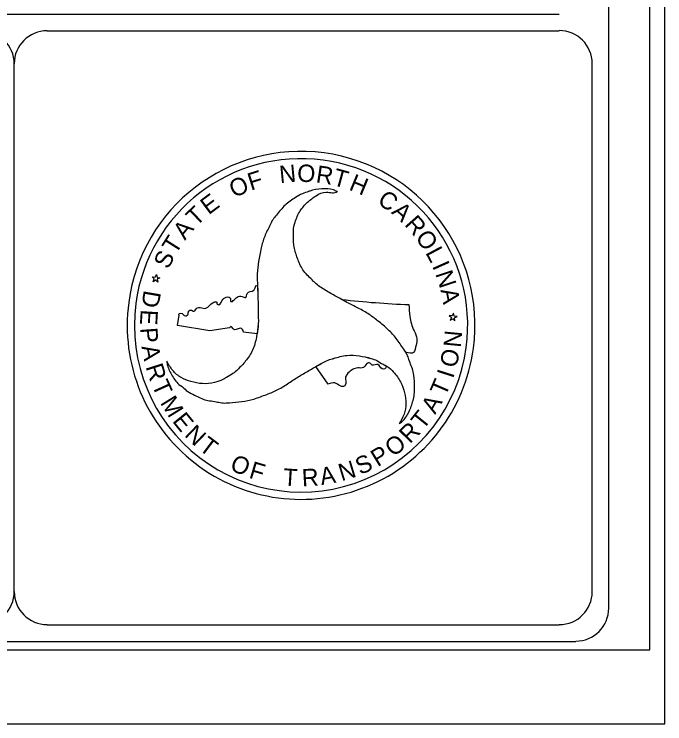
# Model space of a CAD drawing. Extents: x 2163579 to 2286010, y 210234 to 425257.
# Drawn here: x 2258732 to 2271355, y 331036 to 344798 of the extents above; entities that cross this region are included whole.
import ezdxf

# ---------------------------------------------------------------- set-up
doc = ezdxf.new("R2010")
doc.units = 0
for name, color, linetype in [('Sheet Cutting Line CELL', 7, 'Continuous'), ('Sheet Plot Border Inside CELL', 7, 'Continuous'), ('Sheet Plot Border Outside CELL', 7, 'Continuous'), ('Sheet Title CELL', 7, 'Continuous')]:
    doc.layers.add(name, color=color, linetype=linetype)

msp = doc.modelspace()

# ---------------------------------------------------------------- linework, layer by layer
at = {"layer": 'Sheet Cutting Line CELL'}
msp.add_line((2163579, 331036), (2271355, 331036), dxfattribs=at)
at = {"layer": 'Sheet Plot Border Inside CELL'}
msp.add_lwpolyline([(2164411, 332472), (2271067, 332472), (2271067, 399999), (2164411, 399999)], close=True, dxfattribs=at)
at = {"layer": 'Sheet Plot Border Outside CELL'}
msp.add_lwpolyline([(2271355, 401435), (2163579, 401435), (2163579, 331036), (2271355, 331036)], close=True, dxfattribs=at)
at = {"layer": 'Sheet Title CELL'}
for p, q in [((2178427, 344796), (2269307, 344796)), ((2259372, 344476), (2269307, 344476)), ((2258732, 333596), (2258732, 343836)), ((2265005, 341366), (2264998, 341359)), ((2265005, 341366), (2264998, 341359)), ((2261451, 339663), (2261409, 339704)), ((2261409, 339704), (2261468, 339696)), ((2261427, 339610), (2261451, 339663)), ((2261476, 339639), (2261427, 339610)), ((2261468, 339696), (2261491, 339748)), ((2261519, 339598), (2261476, 339639)), ((2261491, 339748), (2261503, 339692)), ((2261503, 339692), (2261561, 339684)), ((2261561, 339684), (2261509, 339656)), ((2261509, 339656), (2261519, 339598)), ((2265089, 339264), (2265089, 339264)), ((2261899, 338762), (2261933, 338963)), ((2267231, 338949), (2267174, 338956)), ((2267174, 338956), (2267217, 338916)), ((2267256, 339000), (2267231, 338949)), ((2267269, 338944), (2267256, 339000)), ((2267217, 338916), (2267193, 338863)), ((2267193, 338863), (2267242, 338891)), ((2267242, 338891), (2267284, 338851)), ((2267326, 338938), (2267269, 338944)), ((2267274, 338909), (2267326, 338938)), ((2267284, 338851), (2267274, 338909)), ((2262530, 338654), (2261899, 338762)), ((2262908, 338713), (2262530, 338654)), ((2263447, 338596), (2263182, 338634)), ((2267642, 338319), (2267642, 338319)), ((2264822, 337623), (2264582, 337965)), ((2264582, 337965), (2264582, 337965))]:
    msp.add_line(p, q, dxfattribs=at)
for points in [[(2270267, 333276), (2270267, 399195)], [(2269947, 333596), (2269947, 343836)], [(2259373, 332956), (2269307, 332956)], [(2174907, 332635), (2269627, 332635)]]:
    msp.add_lwpolyline(points, dxfattribs=at)
for centre, radius, start, end in [((2258092, 343836), 640, 0, 90), ((2259372, 343836), 640, 90, 180), ((2269307, 343839), 640, 0, 90), ((2264298, 338763), 3374, 352.4211, 172.4211), ((2264298, 338763), 3233, 352.4211, 172.4211), ((2267091, 356940), 17788, 258.0996, 258.1992), ((2267091, 356940), 17788, 263.5387, 267.7447), ((2264298, 338763), 3374, 172.4211, 352.4211), ((2264298, 338763), 3233, 172.4211, 352.4211), ((2258093, 333600), 640, 270, 360), ((2259373, 333600), 640, 180, 270), ((2269307, 333599), 640, 270, 360), ((2269627, 333279), 640, 270, 360)]:
    msp.add_arc(centre, radius, start, end, dxfattribs=at)
for points in [[(2264998, 341359), (2264925, 341389), (2264702, 341410), (2264466, 341368), (2264445, 341359), (2264324, 341315), (2264192, 341242), (2263988, 341094), (2263821, 340902), (2263754, 340819), (2263698, 340713), (2263592, 340487), (2263523, 340264), (2263473, 340000), (2263446, 339765), (2263453, 339521), (2263462, 339275), (2263466, 339036), (2263467, 338791), (2263436, 338552), (2263432, 338531), (2263356, 338282), (2263223, 338073), (2263065, 337903), (2262975, 337827), (2262852, 337755), (2262781, 337713), (2262620, 337656), (2262383, 337633), (2262161, 337675), (2261970, 337752), (2261810, 337888), (2261694, 338066)], [(2266200, 336853), (2266259, 336899), (2266390, 337082), (2266471, 337308), (2266477, 337330), (2266496, 337458), (2266499, 337610), (2266476, 337860), (2266390, 338099), (2266354, 338200), (2266289, 338302), (2266146, 338506), (2265989, 338677), (2265784, 338852), (2265594, 338991), (2265379, 339111), (2265162, 339224), (2264955, 339339), (2264738, 339463), (2264549, 339608), (2264534, 339623), (2264353, 339815), (2264239, 340035), (2264170, 340255), (2264153, 340369), (2264152, 340514), (2264148, 340597), (2264182, 340764), (2264280, 340982), (2264426, 341151), (2264589, 341278), (2264787, 341348), (2264998, 341359), (2265005, 341366)], [(2261933, 338963), (2261928, 338982), (2261965, 339000), (2262054, 338949), (2262107, 338983), (2262111, 339024), (2262154, 339059), (2262216, 339038), (2262285, 339105), (2262340, 339110), (2262453, 339095), (2262605, 339212), (2262662, 339213), (2262671, 339175), (2262705, 339164), (2262777, 339267), (2262794, 339281), (2262905, 339309), (2262930, 339285), (2262931, 339234), (2262945, 339223), (2262983, 339243), (2263038, 339296), (2263130, 339329), (2263226, 339304), (2263254, 339382), (2263379, 339444), (2263409, 339488), (2263421, 339534)], [(2263453, 339527), (2263453, 339521), (2263462, 339275), (2263466, 339036), (2263467, 338791), (2263446, 338596)], [(2266334, 338239), (2266289, 338302), (2266146, 338506), (2265989, 338677), (2265784, 338852), (2265594, 338991), (2265379, 339111), (2265162, 339224), (2265089, 339264)], [(2266390, 339165), (2266408, 338935), (2266490, 338657), (2266547, 338503), (2266528, 338380), (2266480, 338236), (2266335, 338240)], [(2263182, 338634), (2263163, 338686), (2263114, 338708), (2263039, 338680), (2262987, 338690), (2262935, 338740), (2262908, 338713)], [(2261694, 338066), (2261707, 337988), (2261800, 337784), (2261953, 337600), (2261971, 337588), (2262072, 337503), (2262201, 337427), (2262431, 337322), (2262679, 337277), (2262784, 337258), (2262909, 337263), (2263152, 337285), (2263379, 337335), (2263635, 337425), (2263849, 337518), (2264060, 337647), (2264267, 337780), (2264473, 337900), (2264686, 338022), (2264907, 338117), (2264931, 338123), (2265185, 338182), (2265430, 338172), (2265653, 338122), (2265768, 338081), (2265888, 338008), (2265965, 337970), (2266092, 337857), (2266229, 337665), (2266304, 337453), (2266333, 337246), (2266295, 337041), (2266200, 336853)], [(2264582, 337965), (2264686, 338022), (2264907, 338117), (2264931, 338123), (2265185, 338182), (2265430, 338172), (2265653, 338122), (2265768, 338081), (2265888, 338008), (2265959, 337972)], [(2265958, 337971), (2265920, 337917), (2265869, 337920), (2265790, 338002), (2265679, 337994), (2265633, 338030), (2265601, 338035), (2265509, 337947), (2265399, 337938), (2265208, 337833), (2265163, 337763), (2265154, 337601), (2265108, 337575), (2265057, 337590), (2264956, 337646), (2264822, 337623)]]:
    msp.add_spline(points, degree=3, dxfattribs=at)

# ---------------------------------------------------------------- texts
for s, height, rotation, p in [('N', 336, 5.4049, (2263891, 341521)), ('O', 337, 357.9068, (2264219, 341550)), ('R', 336, 351.2969, (2264574, 341537)), ('F', 337, 17.4918, (2263324, 341375)), ('T', 337, 344.6472, (2264893, 341488)), ('O', 337, 24.6387, (2263000, 341229)), ('H', 336, 337.5625, (2265210, 341399)), ('E', 335, 36.5781, (2262504, 340897)), ('C', 335, 325.2202, (2265760, 341138)), ('T', 336, 43.6937, (2262265, 340671)), ('A', 336, 317.7231, (2266035, 340945)), ('R', 336, 311.3592, (2266291, 340713)), ('A', 338, 50.7489, (2262045, 340402)), ('T', 337, 57.8012, (2261866, 340126)), ('O', 337, 304.2396, (2266503, 340471)), ('S', 336, 64.1774, (2261725, 339838)), ('L', 336, 298.0059, (2266704, 340175)), ('I', 337, 294.0166, (2266835, 339915)), ('N', 336, 288.3165, (2266900, 339765)), ('D', 336, 260.2741, (2261251, 339457)), ('A', 336, 280.8845, (2267002, 339450)), ('E', 335, 266.562, (2261189, 339076)), ('P', 336, 274.0944, (2261174, 338711)), ('N', 336, 84.6293, (2267395, 338324)), ('A', 336, 280.687, (2261200, 338352)), ('O', 335, 77.3812, (2267310, 337926)), ('R', 336, 287.7556, (2261278, 337961)), ('I', 337, 72.2456, (2267246, 337720)), ('T', 336, 294.4062, (2261395, 337609)), ('T', 336, 66.5957, (2267097, 337371)), ('M', 335, 301.6412, (2261557, 337263)), ('A', 337, 59.5113, (2266899, 337025)), ('E', 336, 309.108, (2261788, 336903)), ('T', 335, 51.4242, (2266666, 336723)), ('N', 337, 316.0795, (2262020, 336624)), ('R', 337, 45.3245, (2266407, 336455)), ('T', 336, 322.9215, (2262296, 336363)), ('O', 337, 38.1354, (2266089, 336201)), ('P', 336, 31.4434, (2265783, 336011)), ('O', 336, 336.2252, (2262897, 335969)), ('S', 335, 24.2515, (2265445, 335856)), ('F', 336, 343.3904, (2263271, 335811)), ('N', 335, 17.041, (2265083, 335738)), ('T', 335, 356.2997, (2263941, 335657)), ('R', 337, 3.2563, (2264322, 335637)), ('A', 335, 10.0094, (2264693, 335663))]:
    msp.add_text(s, height=height, rotation=rotation, dxfattribs=at).set_placement(p)

doc.saveas('drawing.dxf')
